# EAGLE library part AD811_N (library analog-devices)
ANALOG DEVICES
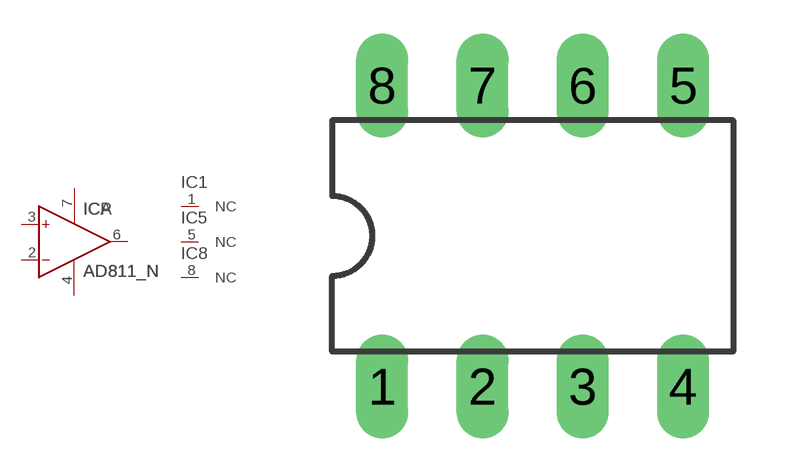
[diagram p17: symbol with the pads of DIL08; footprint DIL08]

Designator prefix IC; gates A=OP P=PWR+- 1=NC 5=NC 8=NC

## AD811_N (MF: ALTERA CORPORATION; MPN: AD811ANZ; OC_FARNELL: 1464857; OC_NEWARK: 58K5191)  [DIL08]
1  1:NC  nc
2  A:IN-  in
3  A:IN+  in
4  P:V-  pwr
5  5:NC  nc
6  A:OUT  out
7  P:V+  pwr
8  8:NC  nc

## Footprint DIL08 (pad centres in mm)
Dual In Line Package
drill 0.813 long: 1 -3.81,-3.81; 2 -1.27,-3.81; 3 1.27,-3.81; 4 3.81,-3.81; 5 3.81,3.81; 6 1.27,3.81; 7 -1.27,3.81; 8 -3.81,3.81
